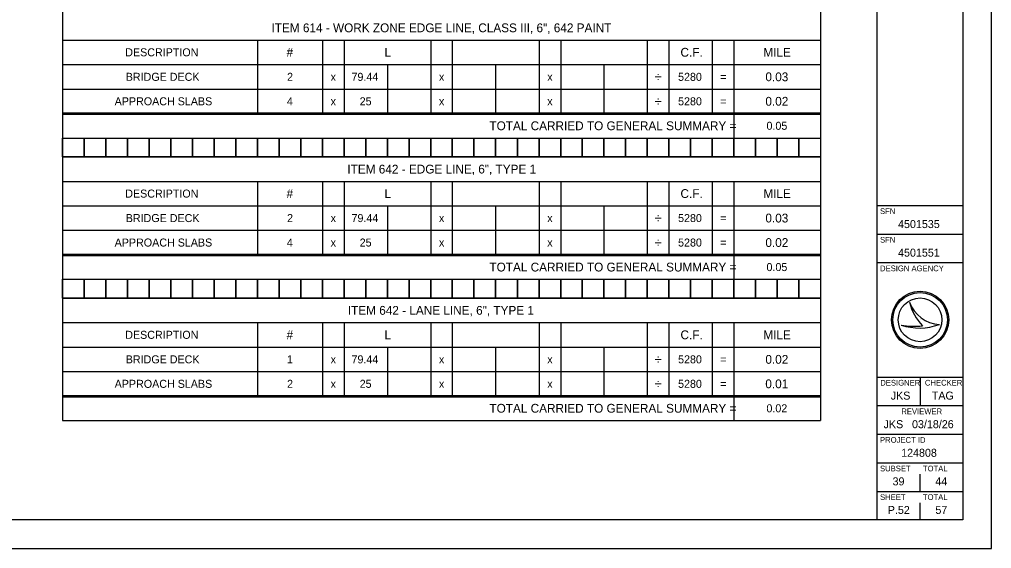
# Model space of a CAD drawing. Extents: x 0 to 34, y 0 to 22.
# Drawn here: x 17 to 34, y 0 to 9.25 of the extents above; entities that cross this region are included whole.
import ezdxf

# ---------------------------------------------------------------- set-up
doc = ezdxf.new("R2010")
doc.units = 0
for name, color, linetype in [('SH_Border', 7, 'Continuous'), ('SH_Cut_Line', 7, 'Continuous'), ('SH_Data', 7, 'Continuous'), ('SH_Text', 7, 'Continuous')]:
    doc.layers.add(name, color=color, linetype=linetype)

msp = doc.modelspace()

# ---------------------------------------------------------------- linework, layer by layer
at = {"layer": 'SH_Border'}
for p, q in [((32, 0.5), (32, 21.5)), ((32, 6), (33.5, 6)), ((32, 5.5), (33.5, 5.5)), ((32, 5), (33.5, 5)), ((32, 3), (33.5, 3)), ((32.75, 3), (32.75, 2.5)), ((32, 2.5), (33.5, 2.5)), ((32, 2), (33.5, 2)), ((32, 1.5), (33.5, 1.5)), ((32, 1), (33.5, 1))]:
    msp.add_line(p, q, dxfattribs=at)
msp.add_lwpolyline([(1.5, 21.5), (33.5, 21.5), (33.5, 0.5), (1.5, 0.5)], close=True, dxfattribs=at)
at = {"layer": 'SH_Cut_Line'}
msp.add_lwpolyline([(0, 0), (34, 0), (34, 22), (0, 22)], close=True, dxfattribs=at)
at = {"layer": 'SH_Data'}
for p, q in [((32.75, 5.675), (32.75, 5.675)), ((32.75, 5.175), (32.75, 5.175)), ((32.567, 4.31), (32.567, 4.31)), ((32.75, 4), (32.75, 4)), ((33.087, 3.919), (33.087, 3.919)), ((32.417, 3.91), (32.417, 3.91)), ((32.75, 1), (32.75, 1.3)), ((32.75, 0.5), (32.75, 0.8)), ((32.375, 0.675), (32.375, 0.675))]:
    msp.add_line(p, q, dxfattribs=at)
for radius in [0.5, 0.477, 0.477, 0.382]:
    msp.add_circle((32.75, 4), radius, dxfattribs=at)
for centre, radius, start, end in [((33.116, 4.498), 0.58, 198.9257, 198.9319), ((33.347, 4.47), 0.796, 191.6379, 191.6421), ((33.116, 4.498), 0.58, 198.9319, 267.1657), ((33.347, 4.47), 0.796, 191.6421, 226.0947), ((32.739, 4.87), 1.013, 251.4576, 290.0832), ((32.648, 5.154), 1.266, 259.4964, 259.4995), ((32.739, 4.87), 1.013, 251.4527, 251.4576), ((32.648, 5.154), 1.266, 259.4995, 276.6672)]:
    msp.add_arc(centre, radius, start, end, dxfattribs=at)
at = {"layer": 'SH_Text'}
for p, q in [((17.752, 10.09), (17.752, 7.597)), ((31.01, 10.09), (31.01, 7.597)), ((17.752, 8.893), (31.01, 8.893)), ((21.161, 8.893), (21.161, 7.619)), ((22.298, 8.893), (22.298, 7.619)), ((22.676, 8.893), (22.676, 7.619)), ((24.192, 8.893), (24.192, 7.619)), ((24.57, 8.893), (24.57, 7.619)), ((26.086, 8.893), (26.086, 7.619)), ((26.465, 8.893), (26.465, 7.619)), ((27.98, 8.893), (27.98, 7.619)), ((28.359, 8.893), (28.359, 7.619)), ((29.116, 8.893), (29.116, 7.619)), ((29.495, 8.893), (29.495, 7.619)), ((17.752, 8.465), (31.01, 8.465)), ((23.434, 8.465), (23.434, 7.619)), ((25.328, 8.465), (25.328, 7.619)), ((27.222, 8.465), (27.222, 7.619)), ((17.752, 8.036), (31.01, 8.036)), ((17.752, 7.619), (31.01, 7.619)), ((17.752, 7.619), (17.752, 5.127)), ((17.752, 7.597), (31.01, 7.597)), ((29.495, 7.597), (29.495, 7.18)), ((31.01, 7.619), (31.01, 5.127)), ((17.752, 7.18), (31.01, 7.18)), ((17.752, 6.85), (31.01, 6.85)), ((17.752, 6.422), (31.01, 6.422)), ((21.161, 6.422), (21.161, 5.149)), ((22.298, 6.422), (22.298, 5.149)), ((22.676, 6.422), (22.676, 5.149)), ((24.192, 6.422), (24.192, 5.149)), ((24.57, 6.422), (24.57, 5.149)), ((26.086, 6.422), (26.086, 5.149)), ((26.465, 6.422), (26.465, 5.149)), ((27.98, 6.422), (27.98, 5.149)), ((28.359, 6.422), (28.359, 5.149)), ((29.116, 6.422), (29.116, 5.149)), ((29.495, 6.422), (29.495, 5.149)), ((17.752, 5.994), (31.01, 5.994)), ((23.434, 5.994), (23.434, 5.149)), ((25.328, 5.994), (25.328, 5.149)), ((27.222, 5.994), (27.222, 5.149)), ((17.752, 5.566), (31.01, 5.566)), ((17.752, 5.149), (31.01, 5.149)), ((17.752, 5.149), (17.752, 2.656)), ((17.752, 5.127), (31.01, 5.127)), ((29.495, 5.127), (29.495, 4.709)), ((31.01, 5.149), (31.01, 2.656)), ((17.752, 4.709), (31.01, 4.709)), ((17.752, 4.38), (31.01, 4.38)), ((17.752, 3.952), (31.01, 3.952)), ((21.161, 3.952), (21.161, 2.678)), ((22.298, 3.952), (22.298, 2.678)), ((22.676, 3.952), (22.676, 2.678)), ((24.192, 3.952), (24.192, 2.678)), ((24.57, 3.952), (24.57, 2.678)), ((26.086, 3.952), (26.086, 2.678)), ((26.465, 3.952), (26.465, 2.678)), ((27.98, 3.952), (27.98, 2.678)), ((28.359, 3.952), (28.359, 2.678)), ((29.116, 3.952), (29.116, 2.678)), ((29.495, 3.952), (29.495, 2.678)), ((17.752, 3.523), (31.01, 3.523)), ((23.434, 3.523), (23.434, 2.678)), ((25.328, 3.523), (25.328, 2.678)), ((27.222, 3.523), (27.222, 2.678)), ((17.752, 3.095), (31.01, 3.095)), ((17.752, 2.678), (31.01, 2.678)), ((17.752, 2.678), (17.752, 2.239)), ((17.752, 2.656), (31.01, 2.656)), ((29.495, 2.656), (29.495, 2.239)), ((31.01, 2.678), (31.01, 2.239)), ((17.752, 2.239), (31.01, 2.239))]:
    msp.add_line(p, q, dxfattribs=at)
for points in [[(17.752, 7.18), (18.13, 7.18), (18.13, 6.85), (17.752, 6.85)], [(18.13, 7.18), (18.509, 7.18), (18.509, 6.85), (18.13, 6.85)], [(18.509, 7.18), (18.888, 7.18), (18.888, 6.85), (18.509, 6.85)], [(18.888, 7.18), (19.267, 7.18), (19.267, 6.85), (18.888, 6.85)], [(19.267, 7.18), (19.646, 7.18), (19.646, 6.85), (19.267, 6.85)], [(19.646, 7.18), (20.025, 7.18), (20.025, 6.85), (19.646, 6.85)], [(20.025, 7.18), (20.403, 7.18), (20.403, 6.85), (20.025, 6.85)], [(20.403, 7.18), (20.782, 7.18), (20.782, 6.85), (20.403, 6.85)], [(20.782, 7.18), (21.161, 7.18), (21.161, 6.85), (20.782, 6.85)], [(21.161, 7.18), (21.54, 7.18), (21.54, 6.85), (21.161, 6.85)], [(21.54, 7.18), (21.919, 7.18), (21.919, 6.85), (21.54, 6.85)], [(21.919, 7.18), (22.298, 7.18), (22.298, 6.85), (21.919, 6.85)], [(22.298, 7.18), (22.676, 7.18), (22.676, 6.85), (22.298, 6.85)], [(22.676, 7.18), (23.055, 7.18), (23.055, 6.85), (22.676, 6.85)], [(23.055, 7.18), (23.434, 7.18), (23.434, 6.85), (23.055, 6.85)], [(23.434, 7.18), (23.813, 7.18), (23.813, 6.85), (23.434, 6.85)], [(23.813, 7.18), (24.192, 7.18), (24.192, 6.85), (23.813, 6.85)], [(24.192, 7.18), (24.57, 7.18), (24.57, 6.85), (24.192, 6.85)], [(24.57, 7.18), (24.949, 7.18), (24.949, 6.85), (24.57, 6.85)], [(24.949, 7.18), (25.328, 7.18), (25.328, 6.85), (24.949, 6.85)], [(25.328, 7.18), (25.707, 7.18), (25.707, 6.85), (25.328, 6.85)], [(25.707, 7.18), (26.086, 7.18), (26.086, 6.85), (25.707, 6.85)], [(26.086, 7.18), (26.465, 7.18), (26.465, 6.85), (26.086, 6.85)], [(26.465, 7.18), (26.843, 7.18), (26.843, 6.85), (26.465, 6.85)], [(26.843, 7.18), (27.222, 7.18), (27.222, 6.85), (26.843, 6.85)], [(27.222, 7.18), (27.601, 7.18), (27.601, 6.85), (27.222, 6.85)], [(27.601, 7.18), (27.98, 7.18), (27.98, 6.85), (27.601, 6.85)], [(27.98, 7.18), (28.359, 7.18), (28.359, 6.85), (27.98, 6.85)], [(28.359, 7.18), (28.738, 7.18), (28.738, 6.85), (28.359, 6.85)], [(28.738, 7.18), (29.116, 7.18), (29.116, 6.85), (28.738, 6.85)], [(29.116, 7.18), (29.495, 7.18), (29.495, 6.85), (29.116, 6.85)], [(29.495, 7.18), (29.874, 7.18), (29.874, 6.85), (29.495, 6.85)], [(29.874, 7.18), (30.253, 7.18), (30.253, 6.85), (29.874, 6.85)], [(30.253, 7.18), (30.632, 7.18), (30.632, 6.85), (30.253, 6.85)], [(30.632, 7.18), (31.01, 7.18), (31.01, 6.85), (30.632, 6.85)], [(17.752, 4.709), (18.13, 4.709), (18.13, 4.38), (17.752, 4.38)], [(18.13, 4.709), (18.509, 4.709), (18.509, 4.38), (18.13, 4.38)], [(18.509, 4.709), (18.888, 4.709), (18.888, 4.38), (18.509, 4.38)], [(18.888, 4.709), (19.267, 4.709), (19.267, 4.38), (18.888, 4.38)], [(19.267, 4.709), (19.646, 4.709), (19.646, 4.38), (19.267, 4.38)], [(19.646, 4.709), (20.025, 4.709), (20.025, 4.38), (19.646, 4.38)], [(20.025, 4.709), (20.403, 4.709), (20.403, 4.38), (20.025, 4.38)], [(20.403, 4.709), (20.782, 4.709), (20.782, 4.38), (20.403, 4.38)], [(20.782, 4.709), (21.161, 4.709), (21.161, 4.38), (20.782, 4.38)], [(21.161, 4.709), (21.54, 4.709), (21.54, 4.38), (21.161, 4.38)], [(21.54, 4.709), (21.919, 4.709), (21.919, 4.38), (21.54, 4.38)], [(21.919, 4.709), (22.298, 4.709), (22.298, 4.38), (21.919, 4.38)], [(22.298, 4.709), (22.676, 4.709), (22.676, 4.38), (22.298, 4.38)], [(22.676, 4.709), (23.055, 4.709), (23.055, 4.38), (22.676, 4.38)], [(23.055, 4.709), (23.434, 4.709), (23.434, 4.38), (23.055, 4.38)], [(23.434, 4.709), (23.813, 4.709), (23.813, 4.38), (23.434, 4.38)], [(23.813, 4.709), (24.192, 4.709), (24.192, 4.38), (23.813, 4.38)], [(24.192, 4.709), (24.57, 4.709), (24.57, 4.38), (24.192, 4.38)], [(24.57, 4.709), (24.949, 4.709), (24.949, 4.38), (24.57, 4.38)], [(24.949, 4.709), (25.328, 4.709), (25.328, 4.38), (24.949, 4.38)], [(25.328, 4.709), (25.707, 4.709), (25.707, 4.38), (25.328, 4.38)], [(25.707, 4.709), (26.086, 4.709), (26.086, 4.38), (25.707, 4.38)], [(26.086, 4.709), (26.465, 4.709), (26.465, 4.38), (26.086, 4.38)], [(26.465, 4.709), (26.843, 4.709), (26.843, 4.38), (26.465, 4.38)], [(26.843, 4.709), (27.222, 4.709), (27.222, 4.38), (26.843, 4.38)], [(27.222, 4.709), (27.601, 4.709), (27.601, 4.38), (27.222, 4.38)], [(27.601, 4.709), (27.98, 4.709), (27.98, 4.38), (27.601, 4.38)], [(27.98, 4.709), (28.359, 4.709), (28.359, 4.38), (27.98, 4.38)], [(28.359, 4.709), (28.738, 4.709), (28.738, 4.38), (28.359, 4.38)], [(28.738, 4.709), (29.116, 4.709), (29.116, 4.38), (28.738, 4.38)], [(29.116, 4.709), (29.495, 4.709), (29.495, 4.38), (29.116, 4.38)], [(29.495, 4.709), (29.874, 4.709), (29.874, 4.38), (29.495, 4.38)], [(29.874, 4.709), (30.253, 4.709), (30.253, 4.38), (29.874, 4.38)], [(30.253, 4.709), (30.632, 4.709), (30.632, 4.38), (30.253, 4.38)], [(30.632, 4.709), (31.01, 4.709), (31.01, 4.38), (30.632, 4.38)]]:
    msp.add_lwpolyline(points, close=True, dxfattribs=at)

# ---------------------------------------------------------------- texts
at = {"layer": 'SH_Data'}
for s, height, p in [('SFN', 0.1, (32.05, 5.85)), ('4501535', 0.14, (32.365, 5.605)), ('SFN', 0.1, (32.05, 5.35)), ('4501551', 0.14, (32.365, 5.105)), ('DESIGN AGENCY', 0.1, (32.05, 4.85)), ('DESIGNER', 0.1, (32.054, 2.85)), ('CHECKER', 0.1, (32.835, 2.85)), ('JKS', 0.14, (32.237, 2.605)), ('TAG', 0.14, (32.955, 2.605)), ('REVIEWER', 0.1, (32.422, 2.35)), ('JKS', 0.14, (32.112, 2.105)), ('03/18/26', 0.14, (32.609, 2.105)), ('PROJECT ID', 0.1, (32.05, 1.85)), ('124808', 0.14, (32.419, 1.605)), ('SUBSET', 0.1, (32.05, 1.35)), ('TOTAL', 0.1, (32.8, 1.35)), ('39', 0.14, (32.269, 1.105)), ('44', 0.14, (33.016, 1.105)), ('SHEET', 0.1, (32.05, 0.85)), ('TOTAL', 0.1, (32.8, 0.85)), ('P.52', 0.14, (32.185, 0.605)), ('57', 0.14, (33.018, 0.605))]:
    msp.add_text(s, height=height, dxfattribs=at).set_placement(p)
at = {"layer": 'SH_Text'}
for s, height, p in [('ITEM 614 - WORK ZONE EDGE LINE, CLASS III, 6", 642 PAINT', 0.154, (21.408, 9.03)), ('DESCRIPTION', 0.14, (18.85, 8.609)), ('#', 0.154, (21.671, 8.602)), ('L', 0.154, (23.383, 8.602)), ('C.F.', 0.154, (28.56, 8.602)), ('MILE', 0.154, (30.009, 8.602)), ('BRIDGE DECK', 0.14, (18.859, 8.18)), ('2', 0.14, (21.68, 8.18)), ('x', 0.14, (22.442, 8.18)), ('79.44', 0.14, (22.807, 8.18)), ('x', 0.14, (24.336, 8.18)), ('x', 0.14, (26.23, 8.18)), ('÷', 0.168, (28.107, 8.166)), ('5280', 0.14, (28.518, 8.18)), ('=', 0.14, (29.256, 8.18)), ('0.03', 0.154, (30.045, 8.173)), ('APPROACH SLABS', 0.14, (18.665, 7.752)), ('4', 0.14, (21.677, 7.752)), ('x', 0.14, (22.442, 7.752)), ('25', 0.14, (22.95, 7.752)), ('x', 0.14, (24.336, 7.752)), ('x', 0.14, (26.23, 7.752)), ('÷', 0.168, (28.107, 7.738)), ('5280', 0.14, (28.518, 7.752)), ('=', 0.14, (29.256, 7.752)), ('0.02', 0.154, (30.045, 7.745)), ('TOTAL CARRIED TO GENERAL SUMMARY =', 0.154, (25.219, 7.317)), ('0.05', 0.14, (30.064, 7.324)), ('ITEM 642 - EDGE LINE, 6", TYPE 1', 0.154, (22.735, 6.559)), ('DESCRIPTION', 0.14, (18.85, 6.138)), ('#', 0.154, (21.671, 6.131)), ('L', 0.154, (23.383, 6.131)), ('C.F.', 0.154, (28.56, 6.131)), ('MILE', 0.154, (30.009, 6.131)), ('BRIDGE DECK', 0.14, (18.859, 5.71)), ('2', 0.14, (21.68, 5.71)), ('x', 0.14, (22.442, 5.71)), ('79.44', 0.14, (22.807, 5.71)), ('x', 0.14, (24.336, 5.71)), ('x', 0.14, (26.23, 5.71)), ('÷', 0.168, (28.107, 5.696)), ('5280', 0.14, (28.518, 5.71)), ('=', 0.14, (29.256, 5.71)), ('0.03', 0.154, (30.045, 5.703)), ('APPROACH SLABS', 0.14, (18.665, 5.282)), ('4', 0.14, (21.677, 5.282)), ('x', 0.14, (22.442, 5.282)), ('25', 0.14, (22.95, 5.282)), ('x', 0.14, (24.336, 5.282)), ('x', 0.14, (26.23, 5.282)), ('÷', 0.168, (28.107, 5.268)), ('5280', 0.14, (28.518, 5.282)), ('=', 0.14, (29.256, 5.282)), ('0.02', 0.154, (30.045, 5.275)), ('TOTAL CARRIED TO GENERAL SUMMARY =', 0.154, (25.219, 4.846)), ('0.05', 0.14, (30.064, 4.853)), ('ITEM 642 - LANE LINE, 6", TYPE 1', 0.154, (22.743, 4.089)), ('DESCRIPTION', 0.14, (18.85, 3.668)), ('#', 0.154, (21.671, 3.661)), ('L', 0.154, (23.383, 3.661)), ('C.F.', 0.154, (28.56, 3.661)), ('MILE', 0.154, (30.009, 3.661)), ('BRIDGE DECK', 0.14, (18.859, 3.239)), ('1', 0.14, (21.679, 3.239)), ('x', 0.14, (22.442, 3.239)), ('79.44', 0.14, (22.807, 3.239)), ('x', 0.14, (24.336, 3.239)), ('x', 0.14, (26.23, 3.239)), ('÷', 0.168, (28.107, 3.225)), ('5280', 0.14, (28.518, 3.239)), ('=', 0.14, (29.256, 3.239)), ('0.02', 0.154, (30.045, 3.232)), ('APPROACH SLABS', 0.14, (18.665, 2.811)), ('2', 0.14, (21.68, 2.811)), ('x', 0.14, (22.442, 2.811)), ('25', 0.14, (22.95, 2.811)), ('x', 0.14, (24.336, 2.811)), ('x', 0.14, (26.23, 2.811)), ('÷', 0.168, (28.107, 2.797)), ('5280', 0.14, (28.518, 2.811)), ('=', 0.14, (29.256, 2.811)), ('0.01', 0.154, (30.044, 2.804)), ('TOTAL CARRIED TO GENERAL SUMMARY =', 0.154, (25.219, 2.376)), ('0.02', 0.14, (30.063, 2.383))]:
    msp.add_text(s, height=height, dxfattribs=at).set_placement(p)

doc.saveas('drawing.dxf')
